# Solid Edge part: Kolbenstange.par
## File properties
Username: bmolnar
Dokumentum tartalom típus: 0
Author: bmolnar
Last saved by: bmolnar
Revision: 85
Sűrűség: 0,000 kg/m^3
Pontosság: 0,990
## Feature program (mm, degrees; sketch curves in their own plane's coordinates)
base feature "unnamed BaseFeature 1"
thread "unnamed Thread 1"
sketch for "unnamed Protrusion 1" plane through (0, 0, -18.3) normal (0, 0, -1) x-axis (0, -1, 0)
  circle centre (0, 0) radius 10
extrude "unnamed Protrusion 1" add finite 13.4 along +normal
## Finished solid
Body 1: solid body, 17 faces, 23 edges, 8 vertices.
  Faces by surface: plane 8, cylinder 4, torus 3, cone 2
  Edges by curve: circle 13, line 6, ellipse 2, intersection 2
Bounding box of the edges (mm; curved faces can reach further): 20.000 x 20.000 x 87.700, from (-10, -10, -31.7) to (10, 10, 56).
Cylindrical faces by radius (mm): R2.9 x1, R4 x1, R5 x1, R10 x1
Conical faces (half-angle, radius in mm at the cone's reference point): 20 deg R3.5 x1, 60 deg R3.55 x1
Toroidal faces (ring radius, tube radius in mm): R3.3 r0.4 x2, R3.8 r1.2 x1
Planar faces by outward normal: +x 1, +z 3, -x 1, -z 1, oblique 2
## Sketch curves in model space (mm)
circle centre (0, 0, -18.3) radius 10
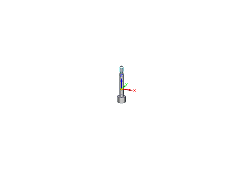
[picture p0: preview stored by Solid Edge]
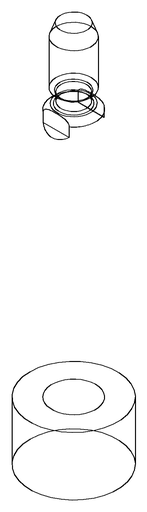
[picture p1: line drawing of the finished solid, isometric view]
